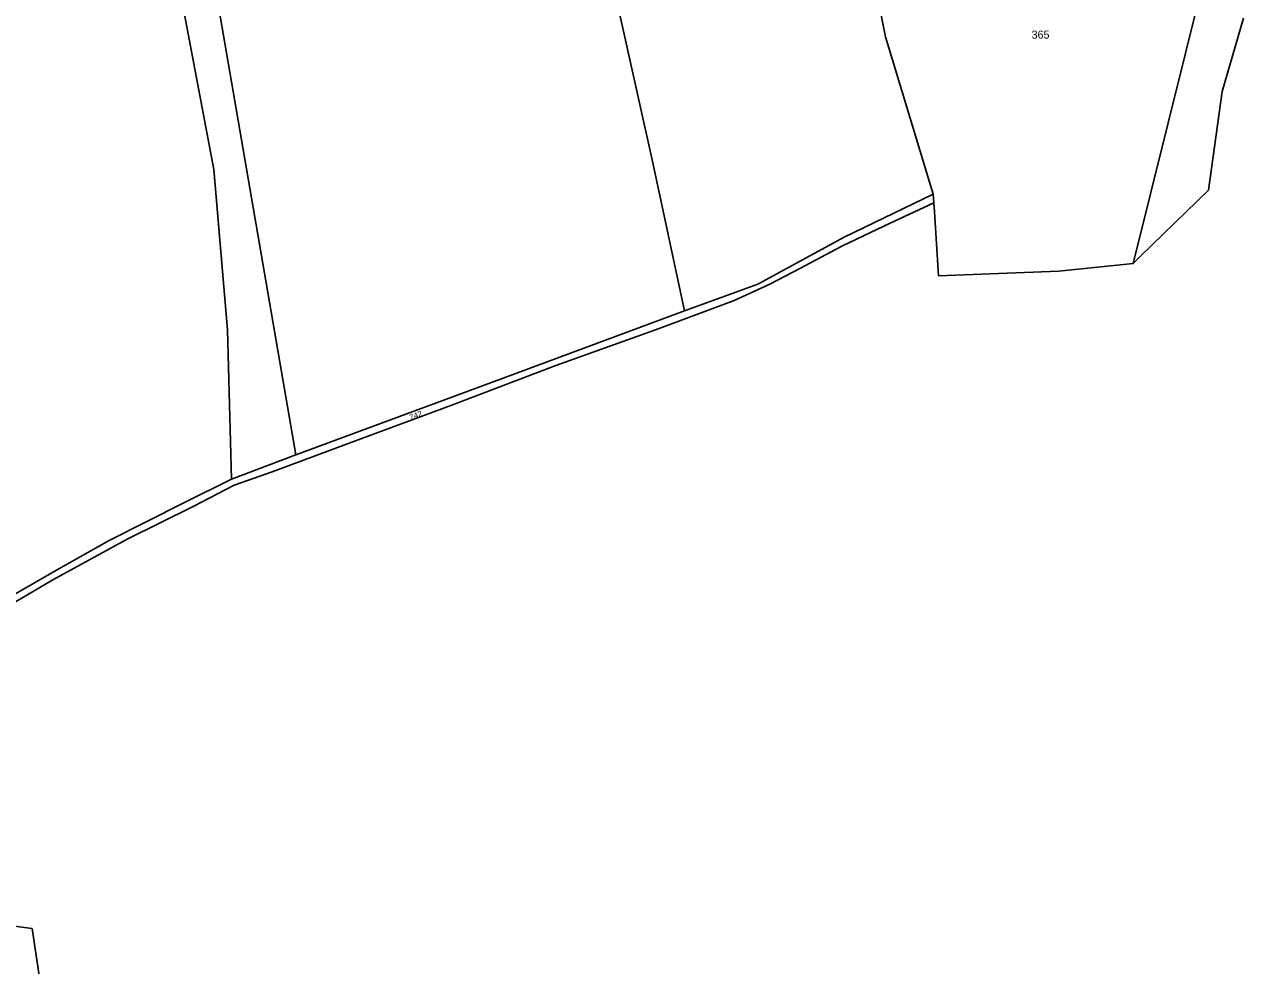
# Model space of a CAD drawing. Extents: x -701211 to -698780, y -1014269 to -1012378.
# Drawn here: x -699060.5 to -698801.5, y -1013138.2 to -1012938.4 of the extents above; entities that cross this region are included whole.
import ezdxf
from ezdxf.enums import TextEntityAlignment as Align

# ---------------------------------------------------------------- set-up
doc = ezdxf.new("R2010")
doc.units = 0
doc.header["$LTSCALE"] = 0.68
doc.layers.add('1', color=7, linetype='Continuous', lineweight=25)
doc.layers.add('2', color=7, linetype='Continuous')

msp = doc.modelspace()

# ---------------------------------------------------------------- linework, layer by layer
at = {"layer": '1'}
for p, q in [((-698877.56, -1012941.07), (-698883.39, -1012912.24)), ((-698813.84, -1012944.54), (-698805.87, -1012912.68)), ((-699020.81, -1012925.37), (-699002.81, -1013029.77)), ((-698927, -1012967.78), (-698935.8, -1012928.08)), ((-699020.23, -1012969.23), (-699027.41, -1012931.15)), ((-698801.49, -1012937.11), (-698806.08, -1012952.68)), ((-698877.56, -1012941.07), (-698867.4, -1012974.44)), ((-698824.94, -1012989.18), (-698813.84, -1012944.54)), ((-698806.08, -1012952.68), (-698808.94, -1012973.59)), ((-698920.28, -1012999.23), (-698927, -1012967.78)), ((-699017.36, -1013003.27), (-699020.23, -1012969.23)), ((-698867.4, -1012974.44), (-698886.35, -1012983.6)), ((-698867.4, -1012974.44), (-698867.3, -1012976.3)), ((-698808.94, -1012973.59), (-698823.36, -1012987.64)), ((-698877.77, -1012981.17), (-698867.3, -1012976.3)), ((-698867.18, -1012978.1), (-698867.3, -1012976.3)), ((-698866.28, -1012991.76), (-698867.18, -1012978.1)), ((-698886.35, -1012983.6), (-698904.66, -1012993.57)), ((-698886.87, -1012985.48), (-698877.77, -1012981.17)), ((-698886.87, -1012985.48), (-698895.73, -1012990.26)), ((-698823.36, -1012987.64), (-698824.94, -1012989.18)), ((-698895.73, -1012990.26), (-698902.15, -1012993.55)), ((-698840.73, -1012990.77), (-698866.28, -1012991.76)), ((-698824.94, -1012989.18), (-698840.73, -1012990.77)), ((-698904.66, -1012993.57), (-698920.28, -1012999.23)), ((-698902.15, -1012993.55), (-698909.74, -1012997.02)), ((-698909.74, -1012997.02), (-698925.63, -1013002.97)), ((-698920.28, -1012999.23), (-698961.24, -1013014.41)), ((-699016.46, -1013034.98), (-699017.36, -1013003.27)), ((-698925.63, -1013002.97), (-698947.62, -1013010.85)), ((-698947.62, -1013010.85), (-698969.89, -1013019.29)), ((-699002.81, -1013029.77), (-698961.24, -1013014.41)), ((-698969.89, -1013019.29), (-698988.98, -1013026.37)), ((-698988.98, -1013026.37), (-699007.87, -1013033.41)), ((-699002.81, -1013029.77), (-699016.46, -1013034.98)), ((-699016.46, -1013034.98), (-699026.58, -1013040.01)), ((-699007.87, -1013033.41), (-699015.88, -1013036.26)), ((-699015.88, -1013036.26), (-699024.6, -1013040.76)), ((-699026.58, -1013040.01), (-699042.47, -1013048)), ((-699024.6, -1013040.76), (-699038.67, -1013047.71)), ((-699038.67, -1013047.71), (-699054.42, -1013056.33)), ((-699042.47, -1013048), (-699053.15, -1013054.02)), ((-699053.15, -1013054.02), (-699066.63, -1013061.73)), ((-699054.42, -1013056.33), (-699069.61, -1013065.19)), ((-699069.35, -1013128.95), (-699058.85, -1013130.36)), ((-699058.85, -1013130.36), (-699054.58, -1013158.71))]:
    msp.add_line(p, q, dxfattribs=at)

# ---------------------------------------------------------------- texts
at = {"layer": '2'}
msp.add_text('365', height=1.7, dxfattribs=at).set_placement((-698844.629, -1012941.425), align=Align.CENTER)
at = {"layer": '2', "width": 1.1}
msp.add_text('742', height=1.14, rotation=21, dxfattribs=at).set_placement((-698977.1233, -1013021.9457), align=Align.CENTER)

doc.saveas('drawing.dxf')
